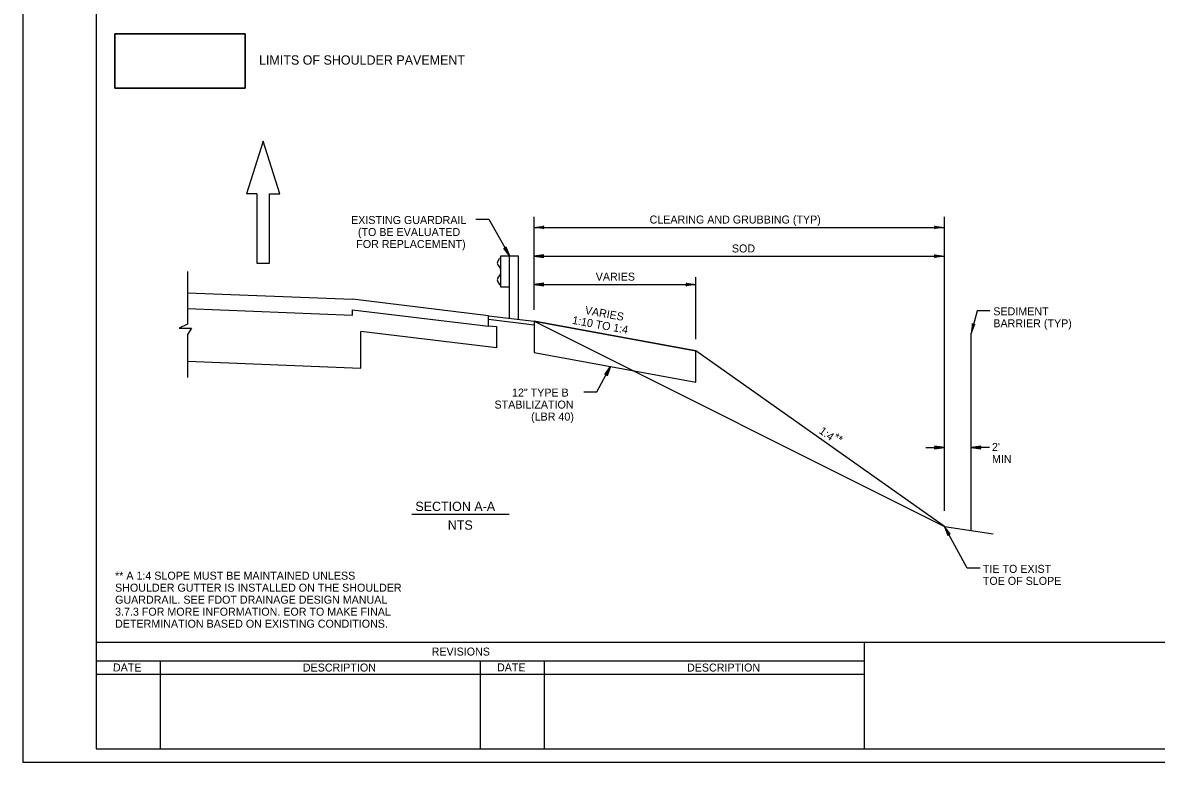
# Model space of a CAD drawing. Extents: x 96794 to 96959, y 32203 to 32309.
# Drawn here: x 96793.8 to 96878.8, y 32202.6 to 32258 of the extents above; entities that cross this region are included whole.
import ezdxf

# ---------------------------------------------------------------- set-up
doc = ezdxf.new("R2010")
doc.units = 0
for name, color, linetype in [('AsphaltMisc', 7, 'Continuous'), ('Base_ex', 7, 'Continuous'), ('BreakLine_dp', 7, 'Continuous'), ('DimLines_dp', 7, 'Continuous'), ('LeaderLine_dp', 7, 'Continuous'), ('Miscellaneous2', 7, 'Continuous'), ('PavtAsph_ep', 7, 'Continuous'), ('PlotBorder_dp', 7, 'Continuous'), ('SheetBorder_dp', 7, 'Continuous'), ('SheetLines_dp', 7, 'Continuous'), ('TextMisc', 7, 'Continuous'), ('TextTitle', 7, 'Continuous'), ('XSTypical_px', 7, 'Continuous')]:
    doc.layers.add(name, color=color, linetype=linetype)

msp = doc.modelspace()

# ---------------------------------------------------------------- linework, layer by layer
at = {"layer": 'AsphaltMisc'}
msp.add_lwpolyline([(96800.715, 32257.145), (96810.49, 32257.145), (96810.49, 32253.081), (96800.715, 32253.081)], close=True, dxfattribs=at)
msp.add_lwpolyline([(96800.715, 32253.081), (96810.49, 32253.081), (96810.49, 32257.145), (96800.715, 32257.145), (96800.715, 32253.081)], dxfattribs=at)
at = {"layer": 'Base_ex'}
for p, q in [((96829.339, 32233.624), (96819.155, 32234.853)), ((96819.155, 32232.094), (96819.155, 32234.853)), ((96828.744, 32235.277), (96829.339, 32235.207)), ((96829.339, 32235.207), (96829.339, 32233.624)), ((96806.17, 32232.611), (96819.155, 32232.094))]:
    msp.add_line(p, q, dxfattribs=at)
at = {"layer": 'BreakLine_dp'}
msp.add_lwpolyline([(96806.17, 32239.349), (96806.17, 32235.403), (96805.546, 32235.097), (96806.466, 32235.097), (96806.159, 32234.606), (96806.159, 32231.4)], dxfattribs=at)
at = {"layer": 'DimLines_dp'}
for p, q in [((96832.153, 32236.474), (96832.153, 32243.45)), ((96862.92, 32221.401), (96862.92, 32243.45)), ((96832.153, 32242.65), (96862.92, 32242.65)), ((96832.153, 32240.483), (96862.92, 32240.483)), ((96832.153, 32238.369), (96844.286, 32238.369)), ((96844.286, 32234.258), (96844.286, 32238.914)), ((96861.523, 32226.147), (96862.92, 32226.147)), ((96861.523, 32226.147), (96862.92, 32226.147)), ((96866.317, 32226.147), (96864.92, 32226.147)), ((96866.317, 32226.147), (96864.92, 32226.147)), ((96822.975, 32221.141), (96830.277, 32221.141))]:
    msp.add_line(p, q, dxfattribs=at)
for points in [[(96832.682, 32242.65), (96832.886, 32242.554), (96832.153, 32242.65), (96832.886, 32242.746), (96832.682, 32242.65)], [(96862.391, 32242.65), (96862.187, 32242.746), (96862.92, 32242.65), (96862.187, 32242.554), (96862.391, 32242.65)], [(96832.682, 32240.483), (96832.886, 32240.579), (96832.153, 32240.483), (96832.886, 32240.387), (96832.682, 32240.483)], [(96862.391, 32240.483), (96862.187, 32240.579), (96862.92, 32240.483), (96862.187, 32240.387), (96862.391, 32240.483)], [(96832.682, 32238.369), (96832.886, 32238.464), (96832.153, 32238.369), (96832.886, 32238.273), (96832.682, 32238.369)], [(96843.757, 32238.369), (96843.553, 32238.464), (96844.286, 32238.369), (96843.553, 32238.273), (96843.757, 32238.369)], [(96862.39, 32226.147), (96862.187, 32226.052), (96862.92, 32226.147), (96862.187, 32226.243), (96862.39, 32226.147)], [(96862.39, 32226.147), (96862.187, 32226.243), (96862.92, 32226.147), (96862.187, 32226.052), (96862.39, 32226.147)], [(96865.45, 32226.147), (96865.653, 32226.052), (96864.92, 32226.147), (96865.653, 32226.243), (96865.45, 32226.147)], [(96865.45, 32226.147), (96865.653, 32226.243), (96864.92, 32226.147), (96865.653, 32226.052), (96865.45, 32226.147)]]:
    msp.add_lwpolyline(points, dxfattribs=at)
at = {"layer": 'LeaderLine_dp'}
for points in [[(96827.788, 32243.263), (96828.755, 32243.263), (96830.321, 32240.506)], [(96830.06, 32240.966), (96830.042, 32241.19), (96830.321, 32240.506), (96829.876, 32241.095), (96830.06, 32240.966)], [(96866.337, 32236.382), (96865.37, 32236.382), (96864.92, 32234.705)], [(96865.057, 32235.216), (96865.018, 32235.438), (96864.92, 32234.705), (96865.203, 32235.388), (96865.057, 32235.216)], [(96835.892, 32230.328), (96836.859, 32230.328), (96837.895, 32232.213)], [(96837.64, 32231.748), (96837.458, 32231.616), (96837.895, 32232.213), (96837.626, 32231.524), (96837.64, 32231.748)], [(96865.603, 32217.116), (96864.637, 32217.116), (96862.92, 32220.239)], [(96863.175, 32219.774), (96863.357, 32219.642), (96862.92, 32220.239), (96863.189, 32219.55), (96863.175, 32219.774)]]:
    msp.add_lwpolyline(points, dxfattribs=at)
at = {"layer": 'Miscellaneous2'}
msp.add_line((96864.92, 32219.928), (96864.92, 32234.705), dxfattribs=at)
at = {"layer": 'PavtAsph_ep'}
for p, q in [((96811.839, 32249.113), (96810.583, 32245.158)), ((96813.094, 32245.158), (96811.839, 32249.113)), ((96811.373, 32245.158), (96810.583, 32245.158)), ((96811.373, 32245.158), (96811.373, 32239.962)), ((96812.304, 32245.158), (96813.094, 32245.158)), ((96812.304, 32239.962), (96812.304, 32245.158)), ((96811.373, 32239.962), (96812.304, 32239.962)), ((96829.422, 32240.101), (96829.565, 32240.307)), ((96829.655, 32240.36), (96829.575, 32240.316)), ((96829.655, 32238.172), (96829.655, 32240.506)), ((96829.655, 32240.506), (96830.988, 32240.506)), ((96830.321, 32235.839), (96830.321, 32240.506)), ((96830.988, 32235.759), (96830.988, 32240.506)), ((96829.422, 32239.847), (96829.622, 32239.56)), ((96829.422, 32238.83), (96829.622, 32239.118)), ((96829.422, 32238.577), (96829.565, 32238.371)), ((96829.655, 32238.318), (96829.575, 32238.362)), ((96806.17, 32237.753), (96818.536, 32237.258)), ((96830.321, 32238.172), (96829.655, 32238.172)), ((96806.17, 32236.57), (96818.536, 32236.076)), ((96828.744, 32236.028), (96818.536, 32237.258)), ((96818.536, 32236.076), (96818.532, 32236.479)), ((96818.532, 32236.479), (96828.741, 32235.249)), ((96828.744, 32235.248), (96828.744, 32236.028)), ((96828.744, 32236.028), (96832.153, 32235.619)), ((96832.153, 32235.329), (96828.744, 32235.738)), ((96832.153, 32235.619), (96862.92, 32220.239)), ((96862.92, 32220.239), (96866.586, 32219.67))]:
    msp.add_line(p, q, dxfattribs=at)
for centre, major_axis, start_param, end_param in [((96829.467, 32239.974), (0, 0.156), 0.622533, 2.519059), ((96829.583, 32240.256), (0, 0.0625), 0.266062, 0.622534), ((96829.577, 32239.433), (0, 0.156), 4.712389, 5.660655), ((96829.577, 32239.245), (0, 0.156), 3.764123, 4.712389), ((96829.467, 32238.704), (0, 0.156), 0.622533, 2.519059), ((96829.583, 32238.422), (0, -0.0625), 5.660652, 6.017123)]:
    msp.add_ellipse(centre, major_axis=major_axis, ratio=0.5, start_param=start_param, end_param=end_param, dxfattribs=at)
at = {"layer": 'PlotBorder_dp'}
msp.add_lwpolyline([(96793.801, 32202.551), (96958.801, 32202.551), (96958.801, 32308.551), (96793.801, 32308.551)], close=True, dxfattribs=at)
at = {"layer": 'SheetBorder_dp'}
for p, q in [((96799.301, 32307.551), (96799.301, 32203.551)), ((96799.301, 32211.551), (96953.301, 32211.551)), ((96799.301, 32203.551), (96953.301, 32203.551))]:
    msp.add_line(p, q, dxfattribs=at)
at = {"layer": 'SheetLines_dp'}
for p, q in [((96856.901, 32211.551), (96856.901, 32203.551)), ((96799.301, 32210.151), (96856.901, 32210.151)), ((96804.101, 32210.151), (96804.101, 32203.551)), ((96828.101, 32210.151), (96828.101, 32203.551)), ((96832.901, 32210.151), (96832.901, 32203.551)), ((96799.301, 32209.151), (96856.901, 32209.151))]:
    msp.add_line(p, q, dxfattribs=at)
at = {"layer": 'XSTypical_px'}
for p, q in [((96832.153, 32235.619), (96832.153, 32233.263)), ((96844.286, 32233.401), (96832.153, 32235.619)), ((96832.153, 32235.619), (96832.153, 32233.263)), ((96832.153, 32233.263), (96844.286, 32231.044)), ((96844.286, 32231.044), (96844.286, 32233.401)), ((96862.92, 32220.239), (96844.286, 32233.401))]:
    msp.add_line(p, q, dxfattribs=at)
for points in [[(96832.153, 32235.619), (96844.286, 32233.401)], [(96832.153, 32233.263), (96844.286, 32231.044)]]:
    msp.add_lwpolyline(points, dxfattribs=at)

# ---------------------------------------------------------------- texts
at = {"layer": 'DimLines_dp'}
for s, p in [('LIMITS OF SHOULDER PAVEMENT', (96811.525, 32254.844)), ('SECTION A-A', (96823.25, 32221.386)), ('NTS', (96825.681, 32219.986))]:
    msp.add_text(s, height=0.7, dxfattribs=at).set_placement(p)
at = {"layer": 'TextMisc'}
for s, p in [('EXISTING GUARDRAIL', (96818.427, 32242.9)), ('CLEARING AND GRUBBING (TYP)', (96840.814, 32242.935)), ('(TO BE EVALUATED', (96818.942, 32242)), ('FOR REPLACEMENT)', (96818.818, 32241.1)), ('SOD', (96846.985, 32240.768)), ('VARIES', (96836.776, 32238.653)), ('SEDIMENT', (96866.592, 32236.057)), ('BARRIER (TYP)', (96866.592, 32235.157)), ('12" TYPE B', (96830.497, 32229.965)), ('STABILIZATION', (96829.184, 32229.065)), ('(LBR 40)', (96831.928, 32228.165)), ("2'", (96866.489, 32225.888)), ('MIN', (96866.489, 32224.988)), ('TIE TO EXIST', (96865.806, 32216.753)), ('** A 1:4 SLOPE MUST BE MAINTAINED UNLESS ', (96800.73, 32216.241)), ('TOE OF SLOPE', (96865.806, 32215.853)), ('SHOULDER GUTTER IS INSTALLED ON THE SHOULDER ', (96800.73, 32215.341)), ('GUARDRAIL. SEE FDOT DRAINAGE DESIGN MANUAL ', (96800.73, 32214.441)), ('3.7.3 FOR MORE INFORMATION. EOR TO MAKE FINAL ', (96800.73, 32213.541)), ('DETERMINATION BASED ON EXISTING CONDITIONS.', (96800.73, 32212.641)), ('REVISIONS', (96824.471, 32210.551))]:
    msp.add_text(s, height=0.6, dxfattribs=at).set_placement(p)
for s, height, rotation, p in [('VARIES', 0.6, 349.63771, (96835.931, 32236.166)), ('1:10 TO 1:4', 0.6, 349.63771, (96834.976, 32235.426)), ('1:4', 0.6, 324.76496, (96853.466, 32227.265)), ('DATE', 0.6, 359.86925, (96800.571, 32209.361)), ('DESCRIPTION', 0.59988, 0.04975, (96814.811, 32209.351)), ('DATE', 0.6, 359.86925, (96829.371, 32209.371)), ('DESCRIPTION', 0.59988, 0.04975, (96843.621, 32209.351))]:
    msp.add_text(s, height=height, rotation=rotation, dxfattribs=at).set_placement(p)
at = {"layer": 'TextTitle'}
msp.add_text('**', height=0.6, rotation=324.76496, dxfattribs=at).set_placement((96854.525, 32226.782))

doc.saveas('drawing.dxf')
